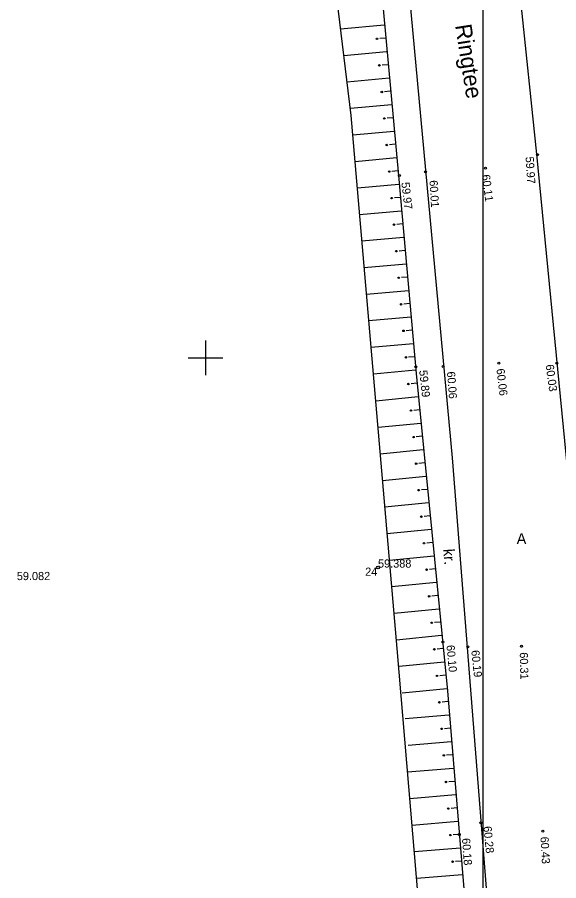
# Model space of a CAD drawing. Extents: x 9156 to 9809, y 2728 to 4000.
# Drawn here: x 9232.7 to 9282.5, y 3501.9 to 3581.3 of the extents above; entities that cross this region are included whole.
import ezdxf

# ---------------------------------------------------------------- set-up
doc = ezdxf.new("R2010")
doc.units = 0
doc.layers.add('Level 54', color=7, linetype='Continuous')
doc.layers.add('Level 63', color=7, linetype='Continuous')

msp = doc.modelspace()

# ---------------------------------------------------------------- linework, layer by layer
at = {"layer": 'Level 54'}
for p, q in [((9263.385, 3572.302), (9257.206, 3623.038)), ((9267.882, 3592.77), (9272.688, 3540.803)), ((9280.477, 3568.73), (9278.071, 3591.482)), ((9262.417, 3580.252), (9266.428, 3580.624)), ((9266.541, 3579.403), (9266.017, 3579.355)), ((9262.713, 3577.818), (9266.654, 3578.183)), ((9266.767, 3576.963), (9266.243, 3576.914)), ((9263.01, 3575.384), (9266.88, 3575.742)), ((9266.993, 3574.522), (9266.469, 3574.474)), ((9263.329, 3572.952), (9267.106, 3573.302)), ((9267.616, 3523.296), (9263.385, 3572.302)), ((9267.219, 3572.081), (9266.695, 3572.033)), ((9263.54, 3570.51), (9267.332, 3570.861)), ((9267.445, 3569.641), (9266.921, 3569.592)), ((9284.599, 3526.285), (9280.477, 3568.73)), ((9263.75, 3568.068), (9267.558, 3568.42)), ((9267.671, 3567.2), (9267.147, 3567.151)), ((9263.96, 3565.637), (9267.783, 3565.98)), ((9267.892, 3564.759), (9267.368, 3564.712)), ((9264.171, 3563.195), (9268.001, 3563.538)), ((9268.11, 3562.317), (9267.587, 3562.271)), ((9264.382, 3560.753), (9268.22, 3561.097)), ((9268.329, 3559.876), (9267.805, 3559.829)), ((9264.593, 3558.311), (9268.438, 3558.655)), ((9268.548, 3557.435), (9268.024, 3557.388)), ((9264.804, 3555.869), (9268.657, 3556.214)), ((9268.766, 3554.993), (9268.242, 3554.946)), ((9265.014, 3553.427), (9268.875, 3553.773)), ((9268.985, 3552.552), (9268.461, 3552.505)), ((9250, 3551.593), (9250, 3548.407)), ((9250, 3551.593), (9250, 3548.407)), ((9250, 3551.593), (9250, 3548.407)), ((9250, 3551.593), (9250, 3548.407)), ((9250, 3551.25), (9250, 3548.75)), ((9265.225, 3550.985), (9269.094, 3551.331)), ((9248.407, 3550), (9250, 3550)), ((9248.407, 3550), (9250, 3550)), ((9248.75, 3550), (9251.25, 3550)), ((9250, 3550), (9251.593, 3550)), ((9250, 3550), (9251.593, 3550)), ((9269.203, 3550.111), (9268.679, 3550.064)), ((9265.436, 3548.543), (9269.312, 3548.89)), ((9269.429, 3547.67), (9268.906, 3547.619)), ((9265.65, 3546.068), (9269.549, 3546.45)), ((9269.669, 3545.23), (9269.145, 3545.179)), ((9265.861, 3543.625), (9269.788, 3544.011)), ((9269.908, 3542.791), (9269.385, 3542.74)), ((9266.072, 3541.183), (9270.028, 3541.571)), ((9270.148, 3540.352), (9269.624, 3540.3)), ((9272.688, 3540.803), (9275.918, 3500)), ((9266.282, 3538.741), (9270.267, 3539.132)), ((9270.387, 3537.912), (9269.864, 3537.861)), ((9266.493, 3536.299), (9270.507, 3536.692)), ((9270.626, 3535.473), (9270.103, 3535.421)), ((9266.704, 3533.856), (9270.746, 3534.253)), ((9270.866, 3533.033), (9270.342, 3532.982)), ((9266.915, 3531.414), (9270.985, 3531.814)), ((9271.105, 3530.594), (9270.582, 3530.543)), ((9267.126, 3528.972), (9271.225, 3529.374)), ((9271.345, 3528.155), (9270.821, 3528.103)), ((9267.337, 3526.53), (9271.464, 3526.935)), ((9271.584, 3525.715), (9271.061, 3525.664)), ((9267.547, 3524.087), (9271.704, 3524.495)), ((9269.604, 3500), (9267.616, 3523.296)), ((9271.823, 3523.276), (9271.3, 3523.224)), ((9267.803, 3521.65), (9271.943, 3522.056)), ((9272.063, 3520.836), (9271.539, 3520.785)), ((9268.079, 3519.214), (9272.182, 3519.617)), ((9272.287, 3518.395), (9271.764, 3518.352)), ((9268.349, 3516.838), (9272.389, 3517.174)), ((9272.49, 3515.953), (9271.966, 3515.909)), ((9268.626, 3514.402), (9272.592, 3514.731)), ((9272.693, 3513.51), (9272.169, 3513.467)), ((9268.585, 3511.939), (9272.795, 3512.289)), ((9272.896, 3511.067), (9272.372, 3511.024)), ((9268.794, 3509.497), (9272.998, 3509.846)), ((9273.099, 3508.625), (9272.575, 3508.581)), ((9269.002, 3507.054), (9273.201, 3507.403)), ((9273.302, 3506.182), (9272.778, 3506.138)), ((9269.21, 3504.612), (9273.404, 3504.961)), ((9273.505, 3503.739), (9272.981, 3503.696)), ((9269.419, 3502.17), (9273.607, 3502.518))]:
    msp.add_line(p, q, dxfattribs=at)
msp.add_lwpolyline([(9273.876, 3500.081), (9272.272, 3519.386), (9269.408, 3548.573), (9267.81, 3566.423), (9265.862, 3587.452), (9263.341, 3611.469), (9261.628, 3624.411), (9261.147, 3625.256), (9258.368, 3625.604), (9250.237, 3627.671)], dxfattribs=at)
for centre, radius in [((9265.762, 3579.339), 0.0683), ((9265.988, 3576.898), 0.0683), ((9266.214, 3574.457), 0.0683), ((9266.44, 3572.017), 0.0683), ((9266.666, 3569.576), 0.0683), ((9280.523, 3568.689), 0.0909), ((9266.892, 3567.135), 0.0683), ((9270.236, 3567.109), 0.0909), ((9275.748, 3567.454), 0.0909), ((9267.824, 3566.763), 0.0909), ((9267.113, 3564.697), 0.0683), ((9267.332, 3562.255), 0.0683), ((9267.55, 3559.814), 0.0683), ((9267.769, 3557.372), 0.0683), ((9267.987, 3554.931), 0.0683), ((9268.206, 3552.49), 0.0683), ((9268.424, 3550.048), 0.0683), ((9276.979, 3549.516), 0.0909), ((9282.295, 3549.516), 0.0909), ((9269.35, 3549.17), 0.0909), ((9271.86, 3549.22), 0.0909), ((9268.651, 3547.601), 0.0683), ((9268.89, 3545.162), 0.0683), ((9269.13, 3542.722), 0.0683), ((9269.369, 3540.283), 0.0683), ((9269.609, 3537.843), 0.0683), ((9269.848, 3535.404), 0.0683), ((9270.087, 3532.964), 0.0683), ((9265.862, 3530.721), 0.125), ((9270.327, 3530.525), 0.0683), ((9270.566, 3528.086), 0.0683), ((9270.806, 3525.646), 0.0683), ((9271.813, 3523.88), 0.0909), ((9274.126, 3523.435), 0.0909), ((9279.048, 3523.485), 0.0909), ((9271.045, 3523.207), 0.0683), ((9271.284, 3520.767), 0.0683), ((9271.508, 3518.338), 0.0683), ((9271.711, 3515.896), 0.0683), ((9271.914, 3513.453), 0.0683), ((9272.117, 3511.01), 0.0683), ((9272.32, 3508.567), 0.0683), ((9275.307, 3507.268), 0.0909), ((9272.523, 3506.125), 0.0683), ((9273.338, 3506.182), 0.0909), ((9281.016, 3506.479), 0.0909), ((9272.726, 3503.682), 0.0683)]:
    msp.add_circle(centre, radius, dxfattribs=at)
at = {"layer": 'Level 63'}
msp.add_lwpolyline([(9275.527, 3966.797), (9801.617, 3966.797), (9801.617, 3329.636), (9275.527, 3329.636)], close=True, dxfattribs=at)

# ---------------------------------------------------------------- texts
at = {"layer": 'Level 54'}
for s, height, rotation, p in [('Ringtee', 1.5, 278.81799, (9272.95, 3580.581)), ('59.97', 0.75, 273.61092, (9279.431, 3568.489)), ('60.01', 0.75, 273.52213, (9270.59, 3566.316)), ('60.11', 0.75, 277.47432, (9275.413, 3566.817)), ('59.97', 0.75, 276.72072, (9268.002, 3566.117)), ('59.89', 0.75, 276.38061, (9269.641, 3548.841)), ('60.06', 0.75, 276.75614, (9276.749, 3548.979)), ('60.03', 0.75, 277.96646, (9281.269, 3549.353)), ('60.06', 0.75, 274.38614, (9272.201, 3548.726)), ('kr.', 1, 273.68076, (9271.868, 3532.419)), ('60.10', 0.75, 275.42451, (9272.152, 3523.573)), ('60.19', 0.75, 275.99185, (9274.435, 3523.096)), ('60.31', 0.75, 271.42791, (9278.895, 3522.927)), ('60.28', 0.75, 275.69413, (9275.55, 3506.912)), ('60.43', 0.75, 273.30138, (9280.798, 3505.962)), ('60.18', 0.75, 274.31255, (9273.582, 3505.821))]:
    msp.add_text(s, height=height, rotation=rotation, dxfattribs=at).set_placement(p)
for s, height, p in [('A', 1, (9278.612, 3532.885)), ('59.388', 0.75, (9265.862, 3530.721)), ('24', 0.75, (9264.681, 3529.971)), ('59.082', 0.75, (9232.645, 3529.573))]:
    msp.add_text(s, height=height, dxfattribs=at).set_placement(p)

doc.saveas('drawing.dxf')
